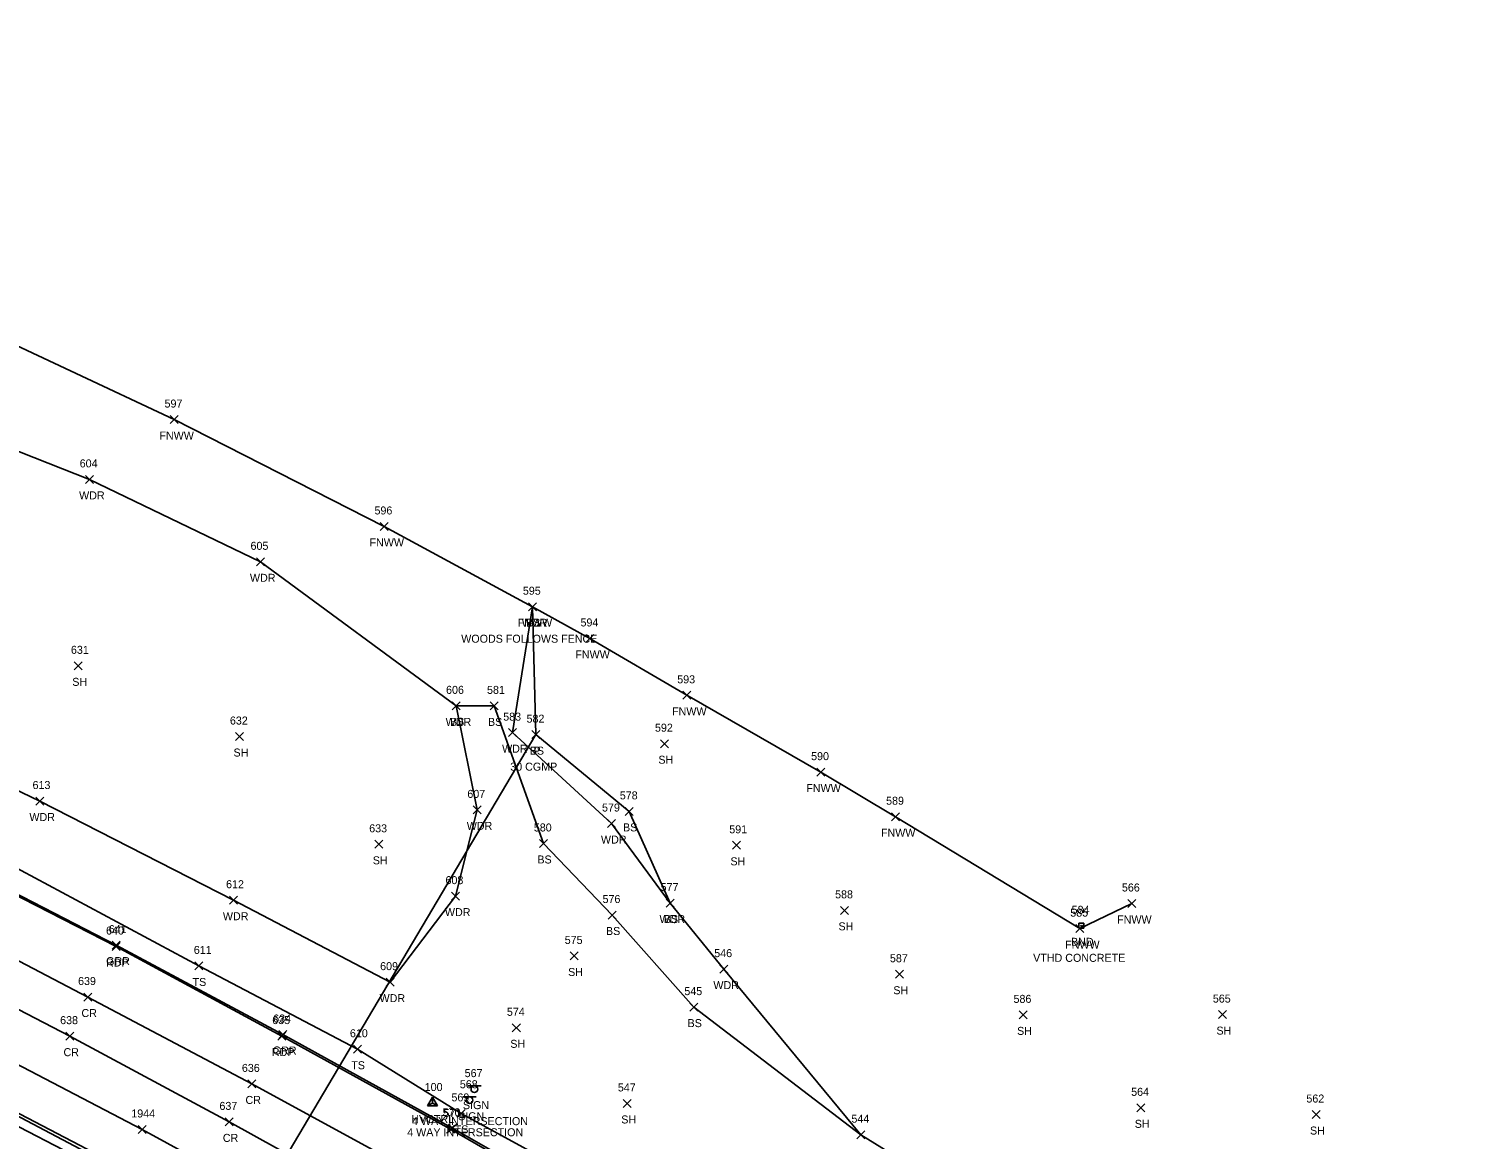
# Model space of a CAD drawing. Extents: x 1629176 to 1637209, y 606063 to 610167.
# Drawn here: x 1630435.7 to 1630792.9, y 606719.6 to 606997.3 of the extents above; entities that cross this region are included whole.
import ezdxf

# ---------------------------------------------------------------- set-up
doc = ezdxf.new("R2010")
doc.units = 0
for name, color, linetype in [('C_A', 7, 'Continuous'), ('C_I', 7, 'Continuous'), ('CPSM', 7, 'Continuous'), ('D_A', 7, 'Continuous'), ('D_C', 7, 'Continuous'), ('D_I', 7, 'Continuous'), ('D_TIC', 7, 'Continuous'), ('DCP', 7, 'Continuous'), ('L_A', 7, 'Continuous'), ('L_C', 7, 'Continuous'), ('L_I', 7, 'Continuous'), ('L_TIC', 7, 'Continuous'), ('LAWA', 7, 'Continuous'), ('LELB', 7, 'Continuous'), ('LFNC', 7, 'Continuous'), ('M_A', 7, 'Continuous'), ('M_C', 7, 'Continuous'), ('M_I', 7, 'Continuous'), ('MHBP', 7, 'Continuous'), ('P_A', 7, 'Continuous'), ('P_I', 7, 'Continuous'), ('P_TIC', 7, 'Continuous'), ('PET', 7, 'Continuous'), ('PRC', 7, 'Continuous'), ('PSP', 7, 'Continuous'), ('R_A', 7, 'Continuous'), ('R_I', 7, 'Continuous'), ('R_TIC', 7, 'Continuous'), ('RGR', 7, 'Continuous'), ('S_A', 7, 'Continuous'), ('S_C', 7, 'Continuous'), ('S_I', 7, 'Continuous'), ('SSGN', 7, 'Continuous')]:
    doc.layers.add(name, color=color, linetype=linetype)

msp = doc.modelspace()

# ---------------------------------------------------------------- linework, layer by layer
at = {"layer": 'CPSM'}
for p, q in [((1630535.35, 606727.98), (1630536.6, 606730.14)), ((1630535.35, 606727.98), (1630536.6, 606728.7)), ((1630537.85, 606727.98), (1630536.6, 606730.14)), ((1630536.6, 606728.7), (1630536.6, 606730.14)), ((1630536.6, 606728.7), (1630536.6, 606728.7)), ((1630536.6, 606728.7), (1630537.85, 606727.98)), ((1630535.35, 606727.98), (1630537.85, 606727.98))]:
    msp.add_line(p, q, dxfattribs=at)
at = {"layer": 'D_TIC'}
for points in [[(1630561.44, 606819.77), (1630563.44, 606821.77)], [(1630563.44, 606819.77), (1630561.44, 606821.77)]]:
    msp.add_lwpolyline(points, dxfattribs=at)
at = {"layer": 'DCP'}
msp.add_lwpolyline([(1630562.44, 606820.77), (1630466.23, 606658.23)], dxfattribs=at)
at = {"layer": 'L_TIC'}
for points in [[(1630471.01, 606898.53), (1630473.01, 606900.53)], [(1630473.01, 606898.53), (1630471.01, 606900.53)], [(1630449.92, 606883.57), (1630451.92, 606885.57)], [(1630451.92, 606883.57), (1630449.92, 606885.57)], [(1630523.5, 606871.81), (1630525.5, 606873.81)], [(1630525.5, 606871.81), (1630523.5, 606873.81)], [(1630492.61, 606862.97), (1630494.61, 606864.97)], [(1630494.61, 606862.97), (1630492.61, 606864.97)], [(1630560.53, 606851.75), (1630562.53, 606853.75)], [(1630562.53, 606851.75), (1630560.53, 606853.75)], [(1630560.53, 606851.75), (1630562.53, 606853.75)], [(1630562.53, 606851.75), (1630560.53, 606853.75)], [(1630560.53, 606851.75), (1630562.53, 606853.75)], [(1630562.53, 606851.75), (1630560.53, 606853.75)], [(1630574.92, 606843.82), (1630576.92, 606845.82)], [(1630576.92, 606843.82), (1630574.92, 606845.82)], [(1630447.09, 606836.97), (1630449.09, 606838.97)], [(1630449.09, 606836.97), (1630447.09, 606838.97)], [(1630541.51, 606826.97), (1630543.51, 606828.97)], [(1630543.51, 606826.97), (1630541.51, 606828.97)], [(1630541.51, 606826.97), (1630543.51, 606828.97)], [(1630543.51, 606826.97), (1630541.51, 606828.97)], [(1630551.01, 606826.96), (1630553.01, 606828.96)], [(1630553.01, 606826.96), (1630551.01, 606828.96)], [(1630599.09, 606829.6), (1630601.09, 606831.6)], [(1630601.09, 606829.6), (1630599.09, 606831.6)], [(1630487.38, 606819.3), (1630489.38, 606821.3)], [(1630489.38, 606819.3), (1630487.38, 606821.3)], [(1630555.61, 606820.27), (1630557.61, 606822.27)], [(1630557.61, 606820.27), (1630555.61, 606822.27)], [(1630561.44, 606819.77), (1630563.44, 606821.77)], [(1630563.44, 606819.77), (1630561.44, 606821.77)], [(1630593.54, 606817.51), (1630595.54, 606819.51)], [(1630595.54, 606817.51), (1630593.54, 606819.51)], [(1630632.63, 606810.4), (1630634.63, 606812.4)], [(1630634.63, 606810.4), (1630632.63, 606812.4)], [(1630437.5, 606803.18), (1630439.5, 606805.18)], [(1630439.5, 606803.18), (1630437.5, 606805.18)], [(1630546.78, 606800.97), (1630548.78, 606802.97)], [(1630548.78, 606800.97), (1630546.78, 606802.97)], [(1630584.75, 606800.59), (1630586.75, 606802.59)], [(1630586.75, 606800.59), (1630584.75, 606802.59)], [(1630651.28, 606799.26), (1630653.28, 606801.26)], [(1630653.28, 606799.26), (1630651.28, 606801.26)], [(1630580.31, 606797.55), (1630582.31, 606799.55)], [(1630582.31, 606797.55), (1630580.31, 606799.55)], [(1630522.18, 606792.36), (1630524.18, 606794.36)], [(1630524.18, 606792.36), (1630522.18, 606794.36)], [(1630563.35, 606792.57), (1630565.35, 606794.57)], [(1630565.35, 606792.57), (1630563.35, 606794.57)], [(1630611.53, 606792.11), (1630613.53, 606794.11)], [(1630613.53, 606792.11), (1630611.53, 606794.11)], [(1630485.85, 606778.39), (1630487.85, 606780.39)], [(1630487.85, 606778.39), (1630485.85, 606780.39)], [(1630541.32, 606779.41), (1630543.32, 606781.41)], [(1630543.32, 606779.41), (1630541.32, 606781.41)], [(1630594.94, 606777.67), (1630596.94, 606779.67)], [(1630596.94, 606777.67), (1630594.94, 606779.67)], [(1630594.94, 606777.67), (1630596.94, 606779.67)], [(1630596.94, 606777.67), (1630594.94, 606779.67)], [(1630710.29, 606777.57), (1630712.29, 606779.57)], [(1630712.29, 606777.57), (1630710.29, 606779.57)], [(1630580.49, 606774.69), (1630582.49, 606776.69)], [(1630582.49, 606774.69), (1630580.49, 606776.69)], [(1630638.53, 606775.86), (1630640.53, 606777.86)], [(1630640.53, 606775.86), (1630638.53, 606777.86)], [(1630697.29, 606771.29), (1630699.29, 606773.29)], [(1630699.29, 606771.29), (1630697.29, 606773.29)], [(1630570.98, 606764.46), (1630572.98, 606766.46)], [(1630572.98, 606764.46), (1630570.98, 606766.46)], [(1630477.23, 606761.96), (1630479.23, 606763.96)], [(1630479.23, 606761.96), (1630477.23, 606763.96)], [(1630608.4, 606761.16), (1630610.4, 606763.16)], [(1630610.4, 606761.16), (1630608.4, 606763.16)], [(1630652.23, 606759.89), (1630654.23, 606761.89)], [(1630654.23, 606759.89), (1630652.23, 606761.89)], [(1630524.99, 606757.91), (1630526.99, 606759.91)], [(1630526.99, 606757.91), (1630524.99, 606759.91)], [(1630600.88, 606751.67), (1630602.88, 606753.67)], [(1630602.88, 606751.67), (1630600.88, 606753.67)], [(1630683.16, 606749.73), (1630685.16, 606751.73)], [(1630685.16, 606749.73), (1630683.16, 606751.73)], [(1630732.96, 606749.8), (1630734.96, 606751.8)], [(1630734.96, 606749.8), (1630732.96, 606751.8)], [(1630556.53, 606746.5), (1630558.53, 606748.5)], [(1630558.53, 606746.5), (1630556.53, 606748.5)], [(1630516.88, 606741.14), (1630518.88, 606743.14)], [(1630518.88, 606741.14), (1630516.88, 606743.14)], [(1630584.25, 606727.59), (1630586.25, 606729.59)], [(1630586.25, 606727.59), (1630584.25, 606729.59)], [(1630712.55, 606726.5), (1630714.55, 606728.5)], [(1630714.55, 606726.5), (1630712.55, 606728.5)], [(1630542.73, 606725.11), (1630544.73, 606727.11)], [(1630544.73, 606725.11), (1630542.73, 606727.11)], [(1630756.33, 606724.82), (1630758.33, 606726.82)], [(1630758.33, 606724.82), (1630756.33, 606726.82)], [(1630642.61, 606719.78), (1630644.61, 606721.78)], [(1630644.61, 606719.78), (1630642.61, 606721.78)], [(1630642.61, 606719.78), (1630644.61, 606721.78)], [(1630644.61, 606719.78), (1630642.61, 606721.78)]]:
    msp.add_lwpolyline(points, dxfattribs=at)
at = {"layer": 'LAWA'}
for points in [[(1630313.82, 606946.86), (1630358.76, 606925.61), (1630402.3, 606903.75), (1630450.92, 606884.57), (1630493.61, 606863.97), (1630542.51, 606827.97), (1630547.78, 606801.97), (1630542.32, 606780.41), (1630525.99, 606758.91), (1630486.85, 606779.39), (1630438.5, 606804.18), (1630398.22, 606823.46), (1630362.92, 606839.59), (1630323.76, 606859.13), (1630280.39, 606881.23), (1630260.08, 606922.64), (1630278.57, 606959.7)], [(1630792.9, 606615.3), (1630764.71, 606631.77), (1630727.23, 606663.62), (1630696.05, 606688.29), (1630643.61, 606720.78), (1630609.4, 606762.16), (1630595.94, 606778.67), (1630581.31, 606798.55), (1630556.61, 606821.27), (1630561.53, 606852.75)]]:
    msp.add_lwpolyline(points, dxfattribs=at)
at = {"layer": 'LELB'}
for points in [[(1630772.3, 606583.26), (1630744.36, 606600.82), (1630702.09, 606628.01), (1630669.73, 606653.69), (1630639.16, 606677.6), (1630625.62, 606682.65), (1630575.5, 606708.79), (1630543.73, 606726.11), (1630517.88, 606742.14), (1630478.23, 606762.96), (1630430.43, 606788.65), (1630392.8, 606806.98), (1630357.66, 606823.31), (1630317.9, 606842.29), (1630273.51, 606862.27), (1630239.69, 606876.29), (1630209.67, 606888.82), (1630166.54, 606905.65), (1630125.1, 606921.22), (1630084.2, 606935.53), (1630049.16, 606947.36)], [(1630044.25, 606889.35), (1630091.41, 606872.59), (1630136.9, 606855.8), (1630181.87, 606838.43), (1630229.1, 606819.13), (1630265.76, 606803.15), (1630304.81, 606785.31), (1630348.18, 606765.13), (1630385.69, 606747.11), (1630426.71, 606726.12), (1630450.89, 606713.6)], [(1630595.94, 606778.67), (1630585.75, 606801.59), (1630562.44, 606820.77), (1630561.53, 606852.75)], [(1630643.61, 606720.78), (1630601.88, 606752.67), (1630581.49, 606775.69), (1630564.35, 606793.57), (1630552.01, 606827.96), (1630542.51, 606827.97)]]:
    msp.add_lwpolyline(points, dxfattribs=at)
at = {"layer": 'LFNC'}
msp.add_lwpolyline([(1630711.29, 606778.57), (1630698.29, 606772.29), (1630652.28, 606800.26), (1630633.63, 606811.4), (1630600.09, 606830.6), (1630575.92, 606844.82), (1630561.53, 606852.75), (1630524.5, 606872.81), (1630472.01, 606899.53), (1630420.14, 606923.9), (1630365.46, 606949.05), (1630323.93, 606967.85), (1630279.06, 606986.64), (1630275.54, 606988.22), (1630271.3, 606989.93), (1630268.56, 606990.98), (1630246.11, 606999.94), (1630223.72, 607008.56), (1630189.18, 607022.51), (1630178, 607040.55), (1630154.89, 607078.39)], dxfattribs=at)
at = {"layer": 'MHBP'}
for p, q in [((1630699.28, 606773.64), (1630698.03, 606773.64)), ((1630698.03, 606773.64), (1630698.03, 606772.39)), ((1630699.28, 606773.64), (1630698.03, 606773.64)), ((1630698.03, 606773.64), (1630698.03, 606772.39)), ((1630698.03, 606772.39), (1630699.28, 606772.39)), ((1630698.03, 606772.39), (1630699.28, 606772.39)), ((1630699.28, 606772.39), (1630699.28, 606773.64)), ((1630699.28, 606772.39), (1630699.28, 606773.64))]:
    msp.add_line(p, q, dxfattribs=at)
msp.add_circle((1630698.63, 606772.98), 0.0833, dxfattribs=at)
at = {"layer": 'P_TIC'}
for points in [[(1630456.51, 606766.81), (1630458.51, 606768.81)], [(1630458.51, 606766.81), (1630456.51, 606768.81)], [(1630449.45, 606754.19), (1630451.45, 606756.19)], [(1630451.45, 606754.19), (1630449.45, 606756.19)], [(1630444.96, 606744.41), (1630446.96, 606746.41)], [(1630446.96, 606744.41), (1630444.96, 606746.41)], [(1630497.96, 606744.43), (1630499.96, 606746.43)], [(1630499.96, 606744.43), (1630497.96, 606746.43)], [(1630490.42, 606732.47), (1630492.42, 606734.47)], [(1630492.42, 606732.47), (1630490.42, 606734.47)], [(1630484.76, 606722.98), (1630486.76, 606724.98)], [(1630486.76, 606722.98), (1630484.76, 606724.98)], [(1630463.02, 606721.09), (1630465.02, 606723.09)], [(1630465.02, 606721.09), (1630463.02, 606723.09)], [(1630540.12, 606721.17), (1630542.12, 606723.17)], [(1630542.12, 606721.17), (1630540.12, 606723.17)]]:
    msp.add_lwpolyline(points, dxfattribs=at)
at = {"layer": 'PET'}
for points in [[(1630769.62, 606580.83), (1630742.32, 606598.72), (1630700.55, 606625.63), (1630665.45, 606648.34), (1630621.98, 606674.98), (1630606.18, 606684.39), (1630572.37, 606704.1), (1630541.12, 606722.17), (1630498.96, 606745.43), (1630457.51, 606767.81), (1630420.78, 606786.67), (1630374.62, 606809.25), (1630335.12, 606827.65), (1630289.38, 606848.42), (1630250.13, 606865.31), (1630203.69, 606884.49), (1630159.86, 606901.83), (1630115.59, 606918.47), (1630070.26, 606934.37)], [(1630050.76, 606901.68), (1630096.23, 606885.67), (1630143.35, 606868.08), (1630186.15, 606851.44), (1630235.05, 606831.31), (1630271.1, 606815.81), (1630310.69, 606798.07), (1630353.79, 606777.93), (1630392.73, 606758.86), (1630432.29, 606738.62), (1630464.02, 606722.09), (1630502.44, 606701.07), (1630537.98, 606680.83), (1630570.03, 606662.27), (1630609.11, 606638.58), (1630644.7, 606616.38), (1630681.38, 606592.72), (1630715.14, 606570.86), (1630750.81, 606547.81)]]:
    msp.add_lwpolyline(points, dxfattribs=at)
at = {"layer": 'PRC'}
for points in [[(1630762, 606568.31), (1630732.48, 606587.66), (1630693.14, 606613.4), (1630657.5, 606636.16), (1630615.44, 606661.97), (1630565.18, 606692.12), (1630533.4, 606710.56), (1630491.42, 606733.47), (1630450.45, 606755.19), (1630412.78, 606774.87), (1630369.5, 606796.13), (1630328.6, 606815.23), (1630283.03, 606835.75), (1630244.34, 606852.21), (1630197.18, 606871.73), (1630154.28, 606888.46), (1630110.18, 606905.77), (1630065.36, 606921.68)], [(1630755.45, 606559.52), (1630726, 606578.65), (1630686.27, 606604.3), (1630651.63, 606626.53), (1630610.5, 606651.79), (1630559.24, 606682.64), (1630527.45, 606700.94), (1630485.76, 606723.98), (1630445.96, 606745.41), (1630407.11, 606765.59), (1630364.16, 606786.66), (1630323.37, 606805.55), (1630278.9, 606825.47), (1630240.3, 606842.26), (1630192.63, 606861.5), (1630149.2, 606878.91), (1630105.99, 606894.95), (1630061.18, 606910.94)]]:
    msp.add_lwpolyline(points, dxfattribs=at)
at = {"layer": 'PSP'}
msp.add_lwpolyline([(1630045.28, 606892.75), (1630092.08, 606875.64), (1630138.49, 606858.75), (1630183.19, 606841.37), (1630230, 606822.13), (1630266.88, 606805.89), (1630306.04, 606788.47), (1630348.79, 606768.34), (1630387.17, 606749.74), (1630427.91, 606728.87), (1630457.64, 606713.36), (1630497.17, 606691.94), (1630531.87, 606672.45), (1630564.31, 606653.82), (1630602.72, 606629.92), (1630638.6, 606607.1), (1630675.39, 606583.77), (1630709.63, 606561.3), (1630744.78, 606538.28)], dxfattribs=at)
at = {"layer": 'R_TIC'}
for points in [[(1630456.55, 606767.16), (1630458.55, 606769.16)], [(1630458.55, 606767.16), (1630456.55, 606769.16)], [(1630498.19, 606744.82), (1630500.19, 606746.82)], [(1630500.19, 606744.82), (1630498.19, 606746.82)], [(1630540.55, 606721.4), (1630542.55, 606723.4)], [(1630542.55, 606721.4), (1630540.55, 606723.4)]]:
    msp.add_lwpolyline(points, dxfattribs=at)
at = {"layer": 'RGR'}
for points in [[(1630636.53, 606670.83), (1630623.24, 606676.36), (1630606.52, 606684.67), (1630573.19, 606704.3), (1630541.55, 606722.4), (1630499.19, 606745.82), (1630457.55, 606768.16), (1630421.01, 606787.01), (1630374.76, 606809.6), (1630335.39, 606828.12), (1630289.48, 606848.85), (1630250.07, 606865.82), (1630203.7, 606885.03), (1630160.01, 606902.28), (1630115.67, 606918.76), (1630070.66, 606934.74)], [(1630044.87, 606891.43), (1630091.95, 606875), (1630137.84, 606857.9), (1630182.67, 606840.57), (1630230.01, 606820.88), (1630266.36, 606805.24), (1630305.77, 606787.45), (1630348.91, 606767.39), (1630386.68, 606748.91), (1630427.72, 606728.18), (1630457.43, 606712.48), (1630496.65, 606691.24), (1630531.18, 606671.77), (1630563.73, 606652.86), (1630574.41, 606646.66), (1630584.49, 606638.94), (1630594.27, 606630.4)]]:
    msp.add_lwpolyline(points, dxfattribs=at)
at = {"layer": 'SSGN'}
for p, q in [((1630545.4, 606733.03), (1630548.73, 606733.03)), ((1630547.04, 606732.19), (1630547.04, 606732.19)), ((1630544.19, 606730.25), (1630547.52, 606730.25)), ((1630545.84, 606729.41), (1630545.84, 606729.41))]:
    msp.add_line(p, q, dxfattribs=at)
for centre in [(1630547.04, 606732.19), (1630545.84, 606729.41)]:
    msp.add_circle(centre, 0.833, dxfattribs=at)

# ---------------------------------------------------------------- texts
at = {"layer": 'C_A'}
msp.add_text('HVCTRL', height=2, dxfattribs=at).set_placement((1630531.29, 606723.7))
at = {"layer": 'C_I'}
msp.add_text('100', height=2, dxfattribs=at).set_placement((1630534.64, 606731.7))
at = {"layer": 'D_A'}
msp.add_text('P', height=2, dxfattribs=at).set_placement((1630561.82, 606815.77))
at = {"layer": 'D_C'}
msp.add_text('30 CGMP', height=2, dxfattribs=at).set_placement((1630556.01, 606811.77))
at = {"layer": 'D_I'}
msp.add_text('582', height=2, dxfattribs=at).set_placement((1630560.08, 606823.77))
at = {"layer": 'L_A'}
for s, p in [('FNWW', (1630468.35, 606894.53)), ('WDR', (1630448.29, 606879.57)), ('FNWW', (1630520.85, 606867.81)), ('WDR', (1630490.97, 606858.97)), ('FNWW', (1630557.87, 606847.75)), ('WDR', (1630558.89, 606847.75)), ('BS', (1630559.97, 606847.75)), ('FNWW', (1630572.27, 606839.82)), ('SH', (1630446.58, 606832.97)), ('WDR', (1630539.87, 606822.97)), ('BS', (1630540.95, 606822.97)), ('BS', (1630550.45, 606822.96)), ('FNWW', (1630596.44, 606825.6)), ('WDR', (1630553.97, 606816.27)), ('BS', (1630560.88, 606815.77)), ('SH', (1630486.87, 606815.3)), ('SH', (1630593.02, 606813.51)), ('FNWW', (1630629.98, 606806.4)), ('WDR', (1630435.87, 606799.18)), ('WDR', (1630545.14, 606796.97)), ('BS', (1630584.19, 606796.59)), ('FNWW', (1630648.63, 606795.26)), ('WDR', (1630578.67, 606793.55)), ('SH', (1630521.67, 606788.36)), ('BS', (1630562.79, 606788.57)), ('SH', (1630611.02, 606788.11)), ('WDR', (1630484.21, 606774.39)), ('WDR', (1630539.68, 606775.41)), ('WDR', (1630593.3, 606773.67)), ('BS', (1630594.38, 606773.67)), ('FNWW', (1630707.64, 606773.57)), ('BS', (1630579.93, 606770.69)), ('SH', (1630638.02, 606771.86)), ('FNWW', (1630694.64, 606767.29)), ('SH', (1630570.47, 606760.46)), ('TS', (1630476.64, 606757.96)), ('WDR', (1630606.76, 606757.16)), ('SH', (1630651.72, 606755.89)), ('WDR', (1630523.35, 606753.91)), ('BS', (1630600.32, 606747.67)), ('SH', (1630682.65, 606745.73)), ('SH', (1630732.45, 606745.8)), ('SH', (1630556.02, 606742.5)), ('TS', (1630516.29, 606737.14)), ('SH', (1630583.74, 606723.59)), ('TS', (1630542.14, 606721.11)), ('SH', (1630712.04, 606722.5)), ('SH', (1630755.82, 606720.82))]:
    msp.add_text(s, height=2, dxfattribs=at).set_placement(p)
at = {"layer": 'L_C'}
for s, p in [('WOODS FOLLOWS FENCE', (1630543.76, 606843.75)), ('WOODS FOLLOWS FENCE', (1630543.76, 606843.75)), ('WOODS FOLLOWS FENCE', (1630543.76, 606843.75)), ('30 CGMP', (1630556.01, 606811.77))]:
    msp.add_text(s, height=2, dxfattribs=at).set_placement(p)
at = {"layer": 'L_I'}
for s, p in [('597', (1630469.64, 606902.53)), ('604', (1630448.44, 606887.57)), ('596', (1630522.09, 606875.81)), ('605', (1630491.12, 606866.97)), ('595', (1630559.16, 606855.75)), ('595', (1630559.16, 606855.75)), ('595', (1630559.16, 606855.75)), ('594', (1630573.56, 606847.82)), ('631', (1630446.25, 606840.97)), ('593', (1630597.73, 606833.6)), ('606', (1630539.97, 606830.97)), ('606', (1630539.97, 606830.97)), ('581', (1630550.21, 606830.96)), ('632', (1630485.97, 606823.3)), ('583', (1630554.25, 606824.27)), ('582', (1630560.08, 606823.77)), ('592', (1630592.17, 606821.51)), ('590', (1630631.18, 606814.4)), ('613', (1630436.66, 606807.18)), ('607', (1630545.29, 606804.97)), ('579', (1630578.94, 606801.55)), ('578', (1630583.38, 606804.59)), ('589', (1630649.91, 606803.26)), ('633', (1630520.77, 606796.36)), ('580', (1630561.9, 606796.57)), ('591', (1630610.73, 606796.11)), ('612', (1630485.01, 606782.39)), ('608', (1630539.83, 606783.41)), ('577', (1630593.58, 606781.67)), ('577', (1630593.58, 606781.67)), ('566', (1630708.83, 606781.57)), ('576', (1630579.07, 606778.69)), ('588', (1630637.17, 606779.86)), ('585', (1630695.93, 606775.29)), ('611', (1630476.95, 606765.96)), ('575', (1630569.62, 606768.46)), ('546', (1630606.98, 606765.16)), ('587', (1630650.87, 606763.89)), ('609', (1630523.5, 606761.91)), ('545', (1630599.51, 606755.67)), ('586', (1630681.75, 606753.73)), ('565', (1630731.55, 606753.8)), ('574', (1630555.17, 606750.5)), ('610', (1630515.95, 606745.14)), ('547', (1630582.89, 606731.59)), ('564', (1630711.14, 606730.5)), ('569', (1630541.32, 606729.11)), ('562', (1630754.92, 606728.82)), ('544', (1630641.25, 606723.78)), ('544', (1630641.25, 606723.78))]:
    msp.add_text(s, height=2, dxfattribs=at).set_placement(p)
at = {"layer": 'M_A'}
msp.add_text('BND', height=2, dxfattribs=at).set_placement((1630696.12, 606767.99))
at = {"layer": 'M_C'}
msp.add_text('VTHD CONCRETE', height=2, dxfattribs=at).set_placement((1630686.65, 606763.99))
at = {"layer": 'M_I'}
msp.add_text('584', height=2, dxfattribs=at).set_placement((1630696.27, 606775.99))
at = {"layer": 'P_A'}
for s, p in [('RDP', (1630455, 606762.81)), ('CR', (1630448.88, 606750.19)), ('CR', (1630444.39, 606740.41)), ('RDP', (1630496.45, 606740.43)), ('CR', (1630489.86, 606728.47)), ('CR', (1630484.2, 606718.98))]:
    msp.add_text(s, height=2, dxfattribs=at).set_placement(p)
at = {"layer": 'P_I'}
for s, p in [('640', (1630455.02, 606770.81)), ('639', (1630448.03, 606758.19)), ('638', (1630443.55, 606748.41)), ('635', (1630496.55, 606748.43)), ('636', (1630488.96, 606736.47)), ('637', (1630483.35, 606726.98)), ('1944', (1630461.33, 606725.09)), ('571', (1630539.33, 606725.17))]:
    msp.add_text(s, height=2, dxfattribs=at).set_placement(p)
at = {"layer": 'R_A'}
for p in [(1630455.04, 606763.16), (1630496.68, 606740.82)]:
    msp.add_text('GRR', height=2, dxfattribs=at).set_placement(p)
at = {"layer": 'R_I'}
for s, p in [('641', (1630455.71, 606771.16)), ('634', (1630496.79, 606748.82)), ('570', (1630539.1, 606725.4))]:
    msp.add_text(s, height=2, dxfattribs=at).set_placement(p)
at = {"layer": 'S_A'}
for p in [(1630544.18, 606727.17), (1630542.98, 606724.39)]:
    msp.add_text('SIGN', height=2, dxfattribs=at).set_placement(p)
at = {"layer": 'S_C'}
for p in [(1630531.47, 606723.17), (1630530.27, 606720.39)]:
    msp.add_text('4 WAY INTERSECTION', height=2, dxfattribs=at).set_placement(p)
at = {"layer": 'S_I'}
for s, p in [('567', (1630544.62, 606735.17)), ('568', (1630543.41, 606732.39))]:
    msp.add_text(s, height=2, dxfattribs=at).set_placement(p)

doc.saveas('drawing.dxf')
